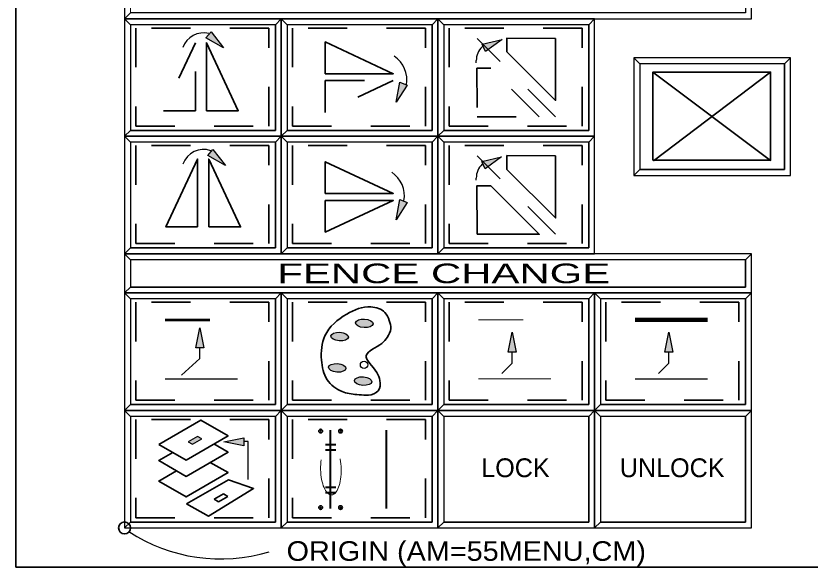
# Model space of a CAD drawing. Extents: x 95906.9 to 95918.9, y 90964.8 to 90972.9.
# Drawn here: x 95906.855 to 95908.882, y 90964.762 to 90966.169 of the extents above; entities that cross this region are included whole.
import ezdxf
from ezdxf.enums import TextEntityAlignment as Align

# ---------------------------------------------------------------- set-up
doc = ezdxf.new("R2010")
doc.units = 0
doc.header["$LTSCALE"] = 0.019
doc.header["$PDMODE"] = 32
doc.header["$PDSIZE"] = 0.0095
for name, pattern in [('DOTTED', [1.5, 0.3, -1.2]), ('LONG_DASHED', [7.5, 6, -1.5]), ('MEDIUM_DASHED', [4.5, 3, -1.5])]:
    doc.linetypes.add(name, pattern=pattern)
for name, color, linetype, lineweight in [('1', 7, 'Continuous', 25), ('11', 7, 'Continuous', 25), ('12', 7, 'Continuous', 25), ('16', 7, 'Continuous', 25), ('18', 7, 'Continuous', 25), ('2', 7, 'Continuous', 13), ('3', 7, 'Continuous', 25), ('4', 7, 'Continuous', 35), ('6', 7, 'Continuous', 35), ('7', 7, 'Continuous', 35)]:
    doc.layers.add(name, color=color, linetype=linetype, lineweight=lineweight)

msp = doc.modelspace()

# ---------------------------------------------------------------- hatches: boundary and pattern name
at = {"layer": '6'}
for points in [[(95907.3851, 90966.0877), (95907.3396, 90966.1133), (95907.3529, 90966.1287)], [(95908.0958, 90966.1092), (95908.0537, 90966.0783), (95908.0451, 90966.0968)], [(95907.8257, 90965.9486), (95907.8349, 90966), (95907.8539, 90965.9925)], [(95907.3901, 90965.7871), (95907.3445, 90965.8126), (95907.3579, 90965.8282)], [(95908.0947, 90965.8094), (95908.0526, 90965.7785), (95908.044, 90965.797)], [(95907.8257, 90965.6486), (95907.8349, 90965.7), (95907.8539, 90965.6925)], [(95907.314, 90965.3216), (95907.3242, 90965.3728), (95907.3344, 90965.3216)], [(95908.1219, 90965.3617), (95908.1321, 90965.3105), (95908.1117, 90965.3105)], [(95908.5219, 90965.3617), (95908.5321, 90965.3105), (95908.5117, 90965.3105)], [(95907.3058, 90965.0753), (95907.3293, 90965.0889), (95907.3181, 90965.0953), (95907.2946, 90965.0817)], [(95907.3857, 90965.0817), (95907.4369, 90965.0919), (95907.4369, 90965.0715)]]:
    msp.add_hatch(color=256, dxfattribs=at).paths.add_polyline_path(points)
h = msp.add_hatch(color=256, dxfattribs=at)
edge = h.paths.add_edge_path()
edge.add_ellipse((95907.7443, 90965.3842), major_axis=(-0.0223, 0.0015), ratio=0.490241, start_angle=0, end_angle=360)
h = msp.add_hatch(color=256, dxfattribs=at)
edge = h.paths.add_edge_path()
edge.add_ellipse((95907.6812, 90965.3504), major_axis=(-0.0223, 0.0015), ratio=0.490241, start_angle=0, end_angle=360)
h = msp.add_hatch(color=256, dxfattribs=at)
edge = h.paths.add_edge_path()
edge.add_ellipse((95907.6751, 90965.2705), major_axis=(-0.0223, 0.0015), ratio=0.490241, start_angle=0, end_angle=360)
h = msp.add_hatch(color=256, dxfattribs=at)
edge = h.paths.add_edge_path()
edge.add_ellipse((95907.7412, 90965.2366), major_axis=(-0.0223, 0.0015), ratio=0.490241, start_angle=0, end_angle=360)

# ---------------------------------------------------------------- linework, layer by layer
at = {"layer": '1'}
for points in [[(95907.1323, 90966.1617), (95908.7323, 90966.1617), (95908.7323, 90966.2617), (95907.1323, 90966.2617)], [(95907.1323, 90965.8617), (95907.5323, 90965.8617), (95907.5323, 90966.1617), (95907.1323, 90966.1617)], [(95907.5323, 90965.8617), (95907.9323, 90965.8617), (95907.9323, 90966.1617), (95907.5323, 90966.1617)], [(95907.9323, 90965.8617), (95908.3323, 90965.8617), (95908.3323, 90966.1617), (95907.9323, 90966.1617)], [(95908.4323, 90965.7617), (95908.8323, 90965.7617), (95908.8323, 90966.0617), (95908.4323, 90966.0617)], [(95907.1323, 90965.5617), (95907.5323, 90965.5617), (95907.5323, 90965.8617), (95907.1323, 90965.8617)], [(95907.5323, 90965.5617), (95907.9323, 90965.5617), (95907.9323, 90965.8617), (95907.5323, 90965.8617)], [(95907.9323, 90965.5617), (95908.3323, 90965.5617), (95908.3323, 90965.8617), (95907.9323, 90965.8617)], [(95907.1323, 90965.4617), (95908.7323, 90965.4617), (95908.7323, 90965.5617), (95907.1323, 90965.5617)], [(95907.1323, 90965.1617), (95907.5323, 90965.1617), (95907.5323, 90965.4617), (95907.1323, 90965.4617)], [(95907.5323, 90965.1617), (95907.9323, 90965.1617), (95907.9323, 90965.4617), (95907.5323, 90965.4617)], [(95907.9323, 90965.1617), (95908.3323, 90965.1617), (95908.3323, 90965.4617), (95907.9323, 90965.4617)], [(95908.3323, 90965.1617), (95908.7323, 90965.1617), (95908.7323, 90965.4617), (95908.3323, 90965.4617)], [(95907.1323, 90964.8617), (95907.5323, 90964.8617), (95907.5323, 90965.1617), (95907.1323, 90965.1617)], [(95907.5323, 90964.8617), (95907.9323, 90964.8617), (95907.9323, 90965.1617), (95907.5323, 90965.1617)], [(95907.9323, 90964.8617), (95908.3323, 90964.8617), (95908.3323, 90965.1617), (95907.9323, 90965.1617)], [(95908.3323, 90964.8617), (95908.7323, 90964.8617), (95908.7323, 90965.1617), (95908.3323, 90965.1617)]]:
    msp.add_lwpolyline(points, close=True, dxfattribs=at)
at = {"layer": '11'}
for points in [[(95907.1473, 90965.8767), (95907.5173, 90965.8767), (95907.5173, 90966.1467), (95907.1473, 90966.1467)], [(95907.5473, 90965.8767), (95907.9173, 90965.8767), (95907.9173, 90966.1467), (95907.5473, 90966.1467)], [(95907.9473, 90965.8767), (95908.3173, 90965.8767), (95908.3173, 90966.1467), (95907.9473, 90966.1467)], [(95907.1473, 90965.5767), (95907.5173, 90965.5767), (95907.5173, 90965.8467), (95907.1473, 90965.8467)], [(95907.5473, 90965.5767), (95907.9173, 90965.5767), (95907.9173, 90965.8467), (95907.5473, 90965.8467)], [(95907.9473, 90965.5767), (95908.3173, 90965.5767), (95908.3173, 90965.8467), (95907.9473, 90965.8467)], [(95907.1473, 90965.1767), (95907.5173, 90965.1767), (95907.5173, 90965.4467), (95907.1473, 90965.4467)], [(95907.5473, 90965.1767), (95907.9173, 90965.1767), (95907.9173, 90965.4467), (95907.5473, 90965.4467)], [(95907.9473, 90965.1767), (95908.3173, 90965.1767), (95908.3173, 90965.4467), (95907.9473, 90965.4467)], [(95908.3473, 90965.1767), (95908.7173, 90965.1767), (95908.7173, 90965.4467), (95908.3473, 90965.4467)], [(95907.1473, 90964.8767), (95907.5173, 90964.8767), (95907.5173, 90965.1467), (95907.1473, 90965.1467)], [(95907.5473, 90964.8767), (95907.9173, 90964.8767), (95907.9173, 90965.1467), (95907.5473, 90965.1467)], [(95907.9473, 90964.8767), (95908.3173, 90964.8767), (95908.3173, 90965.1467), (95907.9473, 90965.1467)], [(95908.3473, 90964.8767), (95908.7173, 90964.8767), (95908.7173, 90965.1467), (95908.3473, 90965.1467)]]:
    msp.add_lwpolyline(points, close=True, dxfattribs=at)
at = {"layer": '12'}
for points in [[(95907.1473, 90965.8767), (95907.5173, 90965.8767), (95907.5173, 90966.1467), (95907.1473, 90966.1467)], [(95908.3473, 90965.1767), (95908.7173, 90965.1767), (95908.7173, 90965.4467), (95908.3473, 90965.4467)]]:
    msp.add_lwpolyline(points, close=True, dxfattribs=at)
at = {"layer": '16'}
msp.add_lwpolyline([(95908.4473, 90965.7767), (95908.8173, 90965.7767), (95908.8173, 90966.0467), (95908.4473, 90966.0467)], close=True, dxfattribs=at)
msp.add_lwpolyline([(95908.4473, 90965.7767), (95908.8173, 90965.7767), (95908.8173, 90966.0467), (95908.4473, 90966.0467)], close=True, dxfattribs=at)
at = {"layer": '18'}
msp.add_lwpolyline([(95907.1473, 90965.4767), (95908.7173, 90965.4767), (95908.7173, 90965.5467), (95907.1473, 90965.5467)], close=True, dxfattribs=at)
at = {"layer": '2'}
for points in [[(95907.1323, 90966.2617), (95907.1323, 90966.1617), (95907.1473, 90966.1767), (95907.1473, 90966.2467), (95908.7173, 90966.2467), (95908.7323, 90966.2617)], [(95907.1323, 90966.1617), (95907.1323, 90965.8617), (95907.1473, 90965.8767), (95907.1473, 90966.1467), (95907.5173, 90966.1467), (95907.5323, 90966.1617)], [(95907.5323, 90966.1617), (95907.5323, 90965.8617), (95907.5473, 90965.8767), (95907.5473, 90966.1467), (95907.9173, 90966.1467), (95907.9323, 90966.1617)], [(95907.9323, 90966.1617), (95907.9323, 90965.8617), (95907.9473, 90965.8767), (95907.9473, 90966.1467), (95908.3173, 90966.1467), (95908.3323, 90966.1617)], [(95908.4323, 90966.0617), (95908.4323, 90965.7617), (95908.4473, 90965.7767), (95908.4473, 90966.0467), (95908.8173, 90966.0467), (95908.8323, 90966.0617)], [(95907.1323, 90965.8617), (95907.1323, 90965.5617), (95907.1473, 90965.5767), (95907.1473, 90965.8467), (95907.5173, 90965.8467), (95907.5323, 90965.8617)], [(95907.5323, 90965.8617), (95907.5323, 90965.5617), (95907.5473, 90965.5767), (95907.5473, 90965.8467), (95907.9173, 90965.8467), (95907.9323, 90965.8617)], [(95907.9323, 90965.8617), (95907.9323, 90965.5617), (95907.9473, 90965.5767), (95907.9473, 90965.8467), (95908.3173, 90965.8467), (95908.3323, 90965.8617)], [(95907.1323, 90965.5617), (95907.1323, 90965.4617), (95907.1473, 90965.4767), (95907.1473, 90965.5467), (95908.7173, 90965.5467), (95908.7323, 90965.5617)], [(95907.1323, 90965.4617), (95907.1323, 90965.1617), (95907.1473, 90965.1767), (95907.1473, 90965.4467), (95907.5173, 90965.4467), (95907.5323, 90965.4617)], [(95907.5323, 90965.4617), (95907.5323, 90965.1617), (95907.5473, 90965.1767), (95907.5473, 90965.4467), (95907.9173, 90965.4467), (95907.9323, 90965.4617)], [(95907.9323, 90965.4617), (95907.9323, 90965.1617), (95907.9473, 90965.1767), (95907.9473, 90965.4467), (95908.3173, 90965.4467), (95908.3323, 90965.4617)], [(95908.3323, 90965.4617), (95908.3323, 90965.1617), (95908.3473, 90965.1767), (95908.3473, 90965.4467), (95908.7173, 90965.4467), (95908.7323, 90965.4617)], [(95907.1323, 90965.1617), (95907.1323, 90964.8617), (95907.1473, 90964.8767), (95907.1473, 90965.1467), (95907.5173, 90965.1467), (95907.5323, 90965.1617)], [(95907.5323, 90965.1617), (95907.5323, 90964.8617), (95907.5473, 90964.8767), (95907.5473, 90965.1467), (95907.9173, 90965.1467), (95907.9323, 90965.1617)], [(95907.9323, 90965.1617), (95907.9323, 90964.8617), (95907.9473, 90964.8767), (95907.9473, 90965.1467), (95908.3173, 90965.1467), (95908.3323, 90965.1617)], [(95908.3323, 90965.1617), (95908.3323, 90964.8617), (95908.3473, 90964.8767), (95908.3473, 90965.1467), (95908.7173, 90965.1467), (95908.7323, 90965.1617)]]:
    msp.add_lwpolyline(points, close=True, dxfattribs=at)
at = {"layer": '3'}
for points in [[(95907.1323, 90966.1617), (95908.7323, 90966.1617), (95908.7323, 90966.2617), (95908.7173, 90966.2467), (95908.7173, 90966.1767), (95907.1473, 90966.1767)], [(95907.1323, 90965.8617), (95907.5323, 90965.8617), (95907.5323, 90966.1617), (95907.5173, 90966.1467), (95907.5173, 90965.8767), (95907.1473, 90965.8767)], [(95907.5323, 90965.8617), (95907.9323, 90965.8617), (95907.9323, 90966.1617), (95907.9173, 90966.1467), (95907.9173, 90965.8767), (95907.5473, 90965.8767)], [(95907.9323, 90965.8617), (95908.3323, 90965.8617), (95908.3323, 90966.1617), (95908.3173, 90966.1467), (95908.3173, 90965.8767), (95907.9473, 90965.8767)], [(95908.4323, 90965.7617), (95908.8323, 90965.7617), (95908.8323, 90966.0617), (95908.8173, 90966.0467), (95908.8173, 90965.7767), (95908.4473, 90965.7767)], [(95907.1323, 90965.5617), (95907.5323, 90965.5617), (95907.5323, 90965.8617), (95907.5173, 90965.8467), (95907.5173, 90965.5767), (95907.1473, 90965.5767)], [(95907.5323, 90965.5617), (95907.9323, 90965.5617), (95907.9323, 90965.8617), (95907.9173, 90965.8467), (95907.9173, 90965.5767), (95907.5473, 90965.5767)], [(95907.9323, 90965.5617), (95908.3323, 90965.5617), (95908.3323, 90965.8617), (95908.3173, 90965.8467), (95908.3173, 90965.5767), (95907.9473, 90965.5767)], [(95907.1323, 90965.4617), (95908.7323, 90965.4617), (95908.7323, 90965.5617), (95908.7173, 90965.5467), (95908.7173, 90965.4767), (95907.1473, 90965.4767)], [(95907.1323, 90965.1617), (95907.5323, 90965.1617), (95907.5323, 90965.4617), (95907.5173, 90965.4467), (95907.5173, 90965.1767), (95907.1473, 90965.1767)], [(95907.5323, 90965.1617), (95907.9323, 90965.1617), (95907.9323, 90965.4617), (95907.9173, 90965.4467), (95907.9173, 90965.1767), (95907.5473, 90965.1767)], [(95907.9323, 90965.1617), (95908.3323, 90965.1617), (95908.3323, 90965.4617), (95908.3173, 90965.4467), (95908.3173, 90965.1767), (95907.9473, 90965.1767)], [(95908.3323, 90965.1617), (95908.7323, 90965.1617), (95908.7323, 90965.4617), (95908.7173, 90965.4467), (95908.7173, 90965.1767), (95908.3473, 90965.1767)], [(95907.1323, 90964.8617), (95907.5323, 90964.8617), (95907.5323, 90965.1617), (95907.5173, 90965.1467), (95907.5173, 90964.8767), (95907.1473, 90964.8767)], [(95907.5323, 90964.8617), (95907.9323, 90964.8617), (95907.9323, 90965.1617), (95907.9173, 90965.1467), (95907.9173, 90964.8767), (95907.5473, 90964.8767)], [(95907.9323, 90964.8617), (95908.3323, 90964.8617), (95908.3323, 90965.1617), (95908.3173, 90965.1467), (95908.3173, 90964.8767), (95907.9473, 90964.8767)], [(95908.3323, 90964.8617), (95908.7323, 90964.8617), (95908.7323, 90965.1617), (95908.7173, 90965.1467), (95908.7173, 90964.8767), (95908.3473, 90964.8767)]]:
    msp.add_lwpolyline(points, close=True, dxfattribs=at)
at = {"layer": '4'}
for p, q in [((95907.1473, 90966.1467), (95907.1323, 90966.1617)), ((95907.5473, 90966.1467), (95907.5323, 90966.1617)), ((95907.9473, 90966.1467), (95907.9323, 90966.1617)), ((95908.4473, 90966.0467), (95908.4323, 90966.0617)), ((95907.1473, 90965.8467), (95907.1323, 90965.8617)), ((95907.5473, 90965.8467), (95907.5323, 90965.8617)), ((95907.9473, 90965.8467), (95907.9323, 90965.8617)), ((95907.1473, 90965.5467), (95907.1323, 90965.5617)), ((95907.1473, 90965.4467), (95907.1323, 90965.4617)), ((95907.5473, 90965.4467), (95907.5323, 90965.4617)), ((95907.9473, 90965.4467), (95907.9323, 90965.4617)), ((95908.3473, 90965.4467), (95908.3323, 90965.4617)), ((95907.1473, 90965.1467), (95907.1323, 90965.1617)), ((95907.5473, 90965.1467), (95907.5323, 90965.1617)), ((95907.9473, 90965.1467), (95907.9323, 90965.1617)), ((95908.3473, 90965.1467), (95908.3323, 90965.1617))]:
    msp.add_line(p, q, dxfattribs=at)
at = {"layer": '6', "linetype": 'MEDIUM_DASHED'}
for p, q in [((95908.2323, 90965.9117), (95908.0323, 90966.1117)), ((95908.2323, 90965.6117), (95908.0323, 90965.8117))]:
    msp.add_line(p, q, dxfattribs=at)
at = {"layer": '6', "lineweight": 25}
for p, q in [((95908.0447, 90966.0902), (95908.0493, 90966.0948)), ((95908.0301, 90966.0495), (95908.0301, 90966.0549)), ((95908.0301, 90965.7495), (95908.0301, 90965.7549)), ((95907.2361, 90965.2424), (95907.4205, 90965.2424)), ((95908.4361, 90965.2424), (95908.6205, 90965.2424))]:
    msp.add_line(p, q, dxfattribs=at)
at = {"layer": '6'}
for p, q in [((95908.4809, 90966.0252), (95908.7809, 90965.8002)), ((95908.4824, 90965.799), (95908.7815, 90966.0252))]:
    msp.add_line(p, q, dxfattribs=at)
at = {"layer": '6', "linetype": 'LONG_DASHED', "lineweight": 53}
msp.add_line((95907.2361, 90965.393), (95907.4205, 90965.393), dxfattribs=at)
at = {"layer": '6', "linetype": 'LONG_DASHED', "lineweight": 13}
msp.add_line((95908.0361, 90965.393), (95908.2205, 90965.393), dxfattribs=at)
at = {"layer": '6', "lineweight": 158}
msp.add_line((95908.4361, 90965.393), (95908.6205, 90965.393), dxfattribs=at)
at = {"layer": '6', "lineweight": 13}
msp.add_line((95908.0361, 90965.2424), (95908.2205, 90965.2424), dxfattribs=at)
at = {"layer": '6', "lineweight": 40}
for p, q in [((95907.6573, 90965.1117), (95907.6573, 90964.9117)), ((95907.8003, 90965.1117), (95907.8003, 90964.9117)), ((95907.6451, 90965.0752), (95907.6713, 90965.0752)), ((95907.6451, 90965.0614), (95907.6713, 90965.0614)), ((95907.6451, 90964.9661), (95907.6713, 90964.9661)), ((95907.6451, 90964.9522), (95907.6713, 90964.9522))]:
    msp.add_line(p, q, dxfattribs=at)
at = {"layer": '6', "linetype": 'DOTTED'}
for points in [[(95907.5007, 90966.1382), (95907.1606, 90966.1382), (95907.1606, 90965.8878), (95907.5007, 90965.8878)], [(95907.5007, 90966.1382), (95907.1606, 90966.1382), (95907.1606, 90965.8878), (95907.5007, 90965.8878)], [(95907.9007, 90966.1382), (95907.5606, 90966.1382), (95907.5606, 90965.8878), (95907.9007, 90965.8878)], [(95908.3007, 90966.1382), (95907.9606, 90966.1382), (95907.9606, 90965.8878), (95908.3007, 90965.8878)], [(95907.5007, 90965.8382), (95907.1606, 90965.8382), (95907.1606, 90965.5878), (95907.5007, 90965.5878)], [(95907.9007, 90965.8382), (95907.5606, 90965.8382), (95907.5606, 90965.5878), (95907.9007, 90965.5878)], [(95908.3007, 90965.8382), (95907.9606, 90965.8382), (95907.9606, 90965.5878), (95908.3007, 90965.5878)], [(95907.5007, 90965.4382), (95907.1606, 90965.4382), (95907.1606, 90965.1878), (95907.5007, 90965.1878)], [(95907.9007, 90965.4382), (95907.5606, 90965.4382), (95907.5606, 90965.1878), (95907.9007, 90965.1878)], [(95908.3007, 90965.4382), (95907.9606, 90965.4382), (95907.9606, 90965.1878), (95908.3007, 90965.1878)], [(95908.7007, 90965.4382), (95908.3606, 90965.4382), (95908.3606, 90965.1878), (95908.7007, 90965.1878)], [(95907.5007, 90965.1382), (95907.1606, 90965.1382), (95907.1606, 90964.8878), (95907.5007, 90964.8878)], [(95907.9007, 90965.1382), (95907.5606, 90965.1382), (95907.5606, 90964.8878), (95907.9007, 90964.8878)]]:
    msp.add_lwpolyline(points, close=True, dxfattribs=at)
at = {"layer": '6', "lineweight": 25}
for points in [[(95907.3851, 90966.0877), (95907.3396, 90966.1133), (95907.3529, 90966.1287)], [(95908.0958, 90966.1092), (95908.0537, 90966.0783), (95908.0451, 90966.0968)], [(95907.8257, 90965.9486), (95907.8349, 90966), (95907.8539, 90965.9925)], [(95907.3901, 90965.7871), (95907.3445, 90965.8126), (95907.3579, 90965.8282)], [(95908.0947, 90965.8094), (95908.0526, 90965.7785), (95908.044, 90965.797)], [(95907.8257, 90965.6486), (95907.8349, 90965.7), (95907.8539, 90965.6925)], [(95907.314, 90965.3216), (95907.3242, 90965.3728), (95907.3344, 90965.3216)], [(95908.1219, 90965.3617), (95908.1321, 90965.3105), (95908.1117, 90965.3105)], [(95908.5219, 90965.3617), (95908.5321, 90965.3105), (95908.5117, 90965.3105)], [(95907.3058, 90965.0753), (95907.3293, 90965.0889), (95907.3181, 90965.0953), (95907.2946, 90965.0817)], [(95907.3857, 90965.0817), (95907.4369, 90965.0919), (95907.4369, 90965.0715)]]:
    msp.add_lwpolyline(points, close=True, dxfattribs=at)
at = {"layer": '6', "linetype": 'MEDIUM_DASHED'}
for points in [[(95907.3129, 90965.9271), (95907.3129, 90966.1005), (95907.2318, 90965.9271)], [(95908.0323, 90965.9117), (95908.1909, 90965.9117), (95908.067, 90966.0356), (95908.0317, 90966.0356)], [(95907.6447, 90966.004), (95907.818, 90966.004), (95907.6447, 90965.9228)], [(95907.3724, 90964.9288), (95907.3959, 90964.9424), (95907.3847, 90964.9488), (95907.3612, 90964.9352)]]:
    msp.add_lwpolyline(points, close=True, dxfattribs=at)
at = {"layer": '6'}
for points in [[(95907.3412, 90965.9271), (95907.3412, 90966.1005), (95907.4224, 90965.9271)], [(95907.6447, 90966.0216), (95907.818, 90966.0216), (95907.6447, 90966.1027)], [(95908.2324, 90966.1118), (95908.2324, 90965.9532), (95908.1085, 90966.0771), (95908.1085, 90966.1124)], [(95908.4812, 90965.8006), (95908.7812, 90965.8006), (95908.7812, 90966.0256), (95908.4812, 90966.0256)], [(95907.3187, 90965.6303), (95907.3187, 90965.8037), (95907.2376, 90965.6303)], [(95907.347, 90965.6303), (95907.347, 90965.8037), (95907.4282, 90965.6303)], [(95907.6447, 90965.7158), (95907.818, 90965.7158), (95907.6447, 90965.7969)], [(95908.2324, 90965.8118), (95908.2324, 90965.6532), (95908.1085, 90965.7771), (95908.1085, 90965.8124)], [(95908.0323, 90965.6117), (95908.1909, 90965.6117), (95908.067, 90965.7356), (95908.0317, 90965.7356)], [(95907.6447, 90965.6982), (95907.818, 90965.6982), (95907.6447, 90965.617)], [(95907.2197, 90965.0752), (95907.3267, 90965.137), (95907.3965, 90965.0967), (95907.2895, 90965.0349)], [(95907.2904, 90964.923), (95907.3974, 90964.9848), (95907.4617, 90964.9625), (95907.3468, 90964.8921)]]:
    msp.add_lwpolyline(points, close=True, dxfattribs=at)
at = {"layer": '6', "lineweight": 25}
for points in [[(95907.2779, 90965.2514), (95907.3242, 90965.2948), (95907.3242, 90965.3216)], [(95908.0956, 90965.2564), (95908.1219, 90965.2827), (95908.1219, 90965.3105)], [(95908.4956, 90965.2564), (95908.5219, 90965.2827), (95908.5219, 90965.3105)], [(95907.4476, 90964.9856), (95907.4476, 90965.0823), (95907.4369, 90965.0823)]]:
    msp.add_lwpolyline(points, dxfattribs=at)
at = {"layer": '6'}
for points in [[(95907.3602, 90965.0763), (95907.3965, 90965.0552), (95907.2895, 90964.9934), (95907.2197, 90965.0337), (95907.2554, 90965.0543)], [(95907.3511, 90965.0292), (95907.3965, 90965.0029), (95907.2895, 90964.9411), (95907.2197, 90964.9814), (95907.265, 90965.0076)]]:
    msp.add_lwpolyline(points, dxfattribs=at)
at = {"layer": '6', "lineweight": 25}
msp.add_circle((95907.7435, 90965.2782), 0.00934, dxfattribs=at)
for centre, radius, start, end in [((95907.334, 90966.0697), 0.0561, 76.2295, 160.6007), ((95908.0801, 90966.0549), 0.05, 135, 180), ((95907.7804, 90966.0054), 0.0727, 350.0158, 56.4113), ((95907.334, 90965.772), 0.0561, 70.6376, 160.6007), ((95908.0801, 90965.7549), 0.05, 135, 180), ((95907.7739, 90965.7097), 0.0727, 350.0158, 56.4113)]:
    msp.add_arc(centre, radius, start, end, dxfattribs=at)
for centre in [(95907.7443, 90965.3842), (95907.6812, 90965.3504), (95907.6751, 90965.2705), (95907.7412, 90965.2366)]:
    msp.add_ellipse(centre, major_axis=(-0.0223, 0.0015), ratio=0.490241, dxfattribs=at)
at = {"layer": '6', "linetype": 'MEDIUM_DASHED', "lineweight": 13}
msp.add_ellipse((95907.6589, 90965.0115), major_axis=(0.0015, -0.0654), ratio=0.400869, dxfattribs=at)
at = {"layer": '6'}
msp.add_spline([(95907.749, 90965.2007), (95907.7252, 90965.2021), (95907.6874, 90965.2101), (95907.6496, 90965.2402), (95907.6349, 90965.2905), (95907.6439, 90965.3524), (95907.6993, 90965.4078), (95907.7611, 90965.426), (95907.7969, 90965.4116), (95907.8079, 90965.3915), (95907.8119, 90965.3711), (95907.8026, 90965.3484), (95907.7892, 90965.333), (95907.7493, 90965.3022), (95907.7761, 90965.259), (95907.7842, 90965.2379), (95907.7795, 90965.2118), (95907.7547, 90965.2007), (95907.749, 90965.2007)], degree=3, dxfattribs=at)
for p in [(95907.6328, 90965.109), (95907.6836, 90965.109), (95907.6328, 90964.9138), (95907.6836, 90964.9138)]:
    msp.add_point(p, dxfattribs=at)
at = {"layer": '7'}
msp.add_lwpolyline([(95906.8548, 90972.8617), (95918.8548, 90972.8617), (95918.8548, 90964.7617), (95906.8548, 90964.7617)], close=True, dxfattribs=at)
msp.add_circle((95907.1323, 90964.8617), 0.0154, dxfattribs=at)
at = {"layer": '7', "lineweight": 25}
msp.add_arc((95907.3775, 90965.209), 0.4264, 236.6831, 286.8865, dxfattribs=at)

# ---------------------------------------------------------------- texts
at = {"layer": '6'}
for s, p in [('LOCK', (95908.1301, 90964.9914)), ('UNLOCK', (95908.5302, 90964.9914))]:
    msp.add_text(s, height=0.048, dxfattribs=at).set_placement(p, align=Align.CENTER)
at = {"layer": '7'}
for s, height, width, p in [('      FENCE CHANGE     ', 0.04999, 1.6, (95907.9322, 90965.4867)), ('ORIGIN (AM=55MENU,CM)', 0.05, 1.1, (95908.0045, 90964.7778))]:
    msp.add_text(s, height=height, dxfattribs=dict(at, width=width)).set_placement(p, align=Align.CENTER)

doc.saveas('drawing.dxf')
